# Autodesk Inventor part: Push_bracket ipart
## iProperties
Shininess: 69.0
Length Units: 11269
Angle Units: 11279
Time Units: 11290
Mass Units: 11283
Length Display Precision: 3
Angle Display Precision: 2
Created: 2001-04
Part Number: Push_bracket ipart
Material: Standard
Document SubType Name: Modellieren
Designer: dl
Density: 1 g/cm^3
Density: 0.0
Volumn: 0.0
Area: 0.0
PropertySet Name: Model Information
Control State: 0
Master: False
Checked Out: False
Author: dl
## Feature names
1. Sweep1
2. Extrusion1
3. Extrusion2
4. Mirror1
